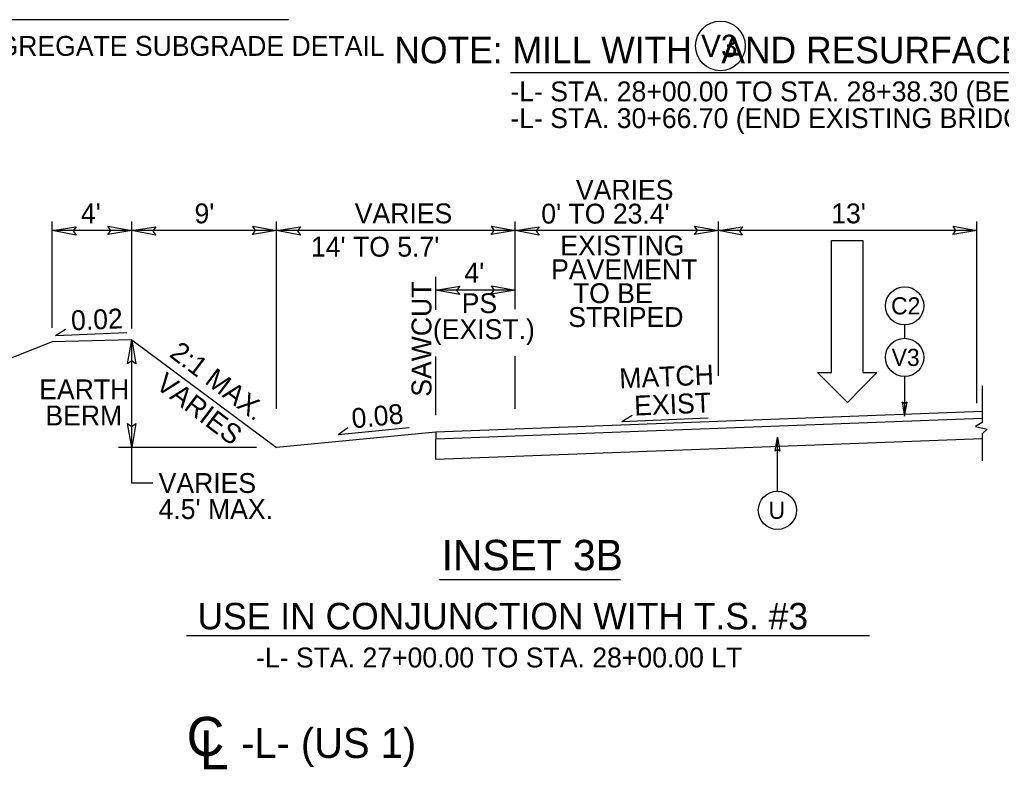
# Model space of a CAD drawing. Extents: x 573748 to 574632, y -54663 to -53209.
# Drawn here: x 574091.7 to 574165.8, y -53610.6 to -53554 of the extents above; entities that cross this region are included whole.
import ezdxf

# ---------------------------------------------------------------- set-up
doc = ezdxf.new("R2010")
doc.units = 0
for name, color, linetype in [('Prop Dimension', 7, 'Continuous'), ('Prop Dimension Text', 7, 'Continuous'), ('Prop Lane Arrow CELL', 7, 'Continuous'), ('Prop Terminator CELL', 7, 'Continuous'), ('Typical Arrow Superelevation CELL', 7, 'Continuous'), ('Typical Hinge Slope Arterial CELL', 7, 'Continuous'), ('Typical ID Circle CELL', 7, 'Continuous'), ('Typical Pavement Slope CELL', 7, 'Continuous'), ('Typical Terminator CELL', 7, 'Continuous'), ('Typical Text Centerline CELL', 7, 'Continuous'), ('Typical Text General CELL', 7, 'Continuous'), ('Typical Text ID Circle CELL', 7, 'Continuous'), ('Typical Text Label CELL', 7, 'Continuous')]:
    doc.layers.add(name, color=color, linetype=linetype)

# ---------------------------------------------------------------- blocks, each defined once
blk = doc.blocks.new('CENTERLINE TEXT CL')
at = {"layer": 'Typical Text Centerline CELL'}
blk.add_text('C', height=1.64, dxfattribs=at).set_placement((-0.546, -0.261))
blk.add_text('L', height=1.641, rotation=359.9469, dxfattribs=at).set_placement((-0.001, -0.821))

msp = doc.modelspace()

# ---------------------------------------------------------------- linework, layer by layer
at = {"layer": 'Prop Dimension'}
for p, q in [((574094.142, -53577.298), (574094.142, -53569.267)), ((574100.142, -53577.356), (574100.142, -53569.267)), ((574111.073, -53583.407), (574111.073, -53569.267)), ((574129.073, -53575.898), (574129.073, -53569.267)), ((574144.407, -53580.921), (574144.407, -53569.267)), ((574163.907, -53582.97), (574163.907, -53569.267)), ((574100.142, -53569.96), (574094.142, -53569.96)), ((574111.073, -53569.96), (574100.142, -53569.96)), ((574129.073, -53569.96), (574111.073, -53569.96)), ((574144.407, -53569.96), (574129.073, -53569.96)), ((574163.907, -53569.96), (574144.407, -53569.96)), ((574123.073, -53575.928), (574123.073, -53573.444)), ((574129.073, -53574.447), (574123.073, -53574.447)), ((574123.073, -53583.877), (574123.073, -53579.471)), ((574129.073, -53583.407), (574129.073, -53579.441)), ((574164.31, -53581.668), (574164.31, -53584.443)), ((574164.31, -53584.443), (574163.804, -53584.739)), ((574163.804, -53584.739), (574164.669, -53584.936)), ((574164.669, -53584.936), (574164.31, -53585.286)), ((574164.31, -53585.678), (574123.073, -53587.221)), ((574123.073, -53587.221), (574123.073, -53585.691)), ((574164.31, -53585.286), (574164.31, -53587.339)), ((574109.555, -53586.326), (574099.145, -53586.326))]:
    msp.add_line(p, q, dxfattribs=at)
msp.add_lwpolyline([(574101.742, -53589.024), (574100.142, -53589.024), (574100.142, -53578.213)], dxfattribs=at)
at = {"layer": 'Prop Lane Arrow CELL'}
for p, q in [((574152.941, -53580.677), (574152.941, -53570.702)), ((574152.941, -53570.702), (574155.292, -53570.702)), ((574155.292, -53570.702), (574155.292, -53580.677)), ((574154.152, -53582.922), (574151.872, -53580.677)), ((574151.872, -53580.677), (574152.941, -53580.677)), ((574156.361, -53580.677), (574154.152, -53582.922)), ((574155.292, -53580.677), (574156.361, -53580.677))]:
    msp.add_line(p, q, dxfattribs=at)
at = {"layer": 'Prop Terminator CELL'}
for points in [[(574095.939, -53570.293), (574094.142, -53569.96), (574095.957, -53569.663), (574095.723, -53569.98)], [(574098.346, -53569.627), (574100.142, -53569.96), (574098.328, -53570.257), (574098.562, -53569.939)], [(574101.939, -53570.293), (574100.142, -53569.96), (574101.957, -53569.663), (574101.723, -53569.98)], [(574109.277, -53569.627), (574111.073, -53569.96), (574109.258, -53570.257), (574109.493, -53569.939)], [(574112.869, -53570.293), (574111.073, -53569.96), (574112.888, -53569.663), (574112.653, -53569.98)], [(574127.277, -53569.627), (574129.073, -53569.96), (574127.258, -53570.257), (574127.493, -53569.939)], [(574130.869, -53570.293), (574129.073, -53569.96), (574130.888, -53569.663), (574130.653, -53569.98)], [(574142.611, -53569.627), (574144.407, -53569.96), (574142.592, -53570.257), (574142.827, -53569.939)], [(574146.203, -53570.293), (574144.407, -53569.96), (574146.222, -53569.663), (574145.987, -53569.98)], [(574162.111, -53569.627), (574163.907, -53569.96), (574162.092, -53570.257), (574162.327, -53569.939)], [(574124.869, -53574.781), (574123.073, -53574.447), (574124.888, -53574.151), (574124.653, -53574.468)], [(574127.277, -53574.114), (574129.073, -53574.447), (574127.258, -53574.744), (574127.493, -53574.427)], [(574099.832, -53580.014), (574100.142, -53578.213), (574100.462, -53580.024), (574100.142, -53579.794)], [(574100.452, -53584.526), (574100.142, -53586.326), (574099.822, -53584.516), (574100.142, -53584.746)]]:
    msp.add_lwpolyline(points, close=True, dxfattribs=at)
at = {"layer": 'Typical Arrow Superelevation CELL'}
for p, q in [((574094.384, -53577.88), (574095.156, -53577.39)), ((574094.384, -53577.88), (574099.773, -53577.657)), ((574137.12, -53584.368), (574137.892, -53583.877)), ((574137.12, -53584.368), (574143.638, -53584.088)), ((574115.705, -53585.347), (574121.072, -53584.805)), ((574115.705, -53585.347), (574116.447, -53584.812))]:
    msp.add_line(p, q, dxfattribs=at)
at = {"layer": 'Typical Hinge Slope Arterial CELL'}
for p, q in [((574094.142, -53578.346), (574071.464, -53587.365)), ((574100.142, -53578.213), (574094.142, -53578.346)), ((574100.142, -53578.213), (574111.073, -53586.326))]:
    msp.add_line(p, q, dxfattribs=at)
at = {"layer": 'Typical ID Circle CELL'}
for p, q in [((574158.452, -53577.08), (574158.452, -53578.085)), ((574158.452, -53580.971), (574158.452, -53583.957)), ((574148.857, -53589.623), (574148.857, -53585.539))]:
    msp.add_line(p, q, dxfattribs=at)
for centre, radius in [((574144.55, -53556.021), 1.875), ((574158.452, -53575.638), 1.443), ((574158.452, -53579.528), 1.443), ((574148.857, -53591.065), 1.443)]:
    msp.add_circle(centre, radius, dxfattribs=at)
at = {"layer": 'Typical Pavement Slope CELL'}
for p, q in [((574164.31, -53583.621), (574123.073, -53585.164)), ((574164.31, -53584.148), (574123.073, -53585.691)), ((574123.073, -53585.164), (574111.073, -53586.326)), ((574123.073, -53585.164), (574123.073, -53585.691))]:
    msp.add_line(p, q, dxfattribs=at)
at = {"layer": 'Typical Terminator CELL'}
for points in [[(574158.271, -53582.903), (574158.452, -53583.957), (574158.64, -53582.897), (574158.452, -53583.031)], [(574148.676, -53586.594), (574148.857, -53585.539), (574149.045, -53586.599), (574148.857, -53586.465)]]:
    msp.add_lwpolyline(points, close=True, dxfattribs=at)
at = {"layer": 'Typical Text General CELL'}
for p, q in [((574128.708, -53558.022), (574181.37, -53558.022)), ((574155.804, -53600.549), (574104.275, -53600.549))]:
    msp.add_line(p, q, dxfattribs=at)
at = {"layer": 'Typical Text Label CELL'}
for p, q in [((574071.117, -53554.037), (574111.959, -53554.037)), ((574137.016, -53596.317), (574123.356, -53596.317))]:
    msp.add_line(p, q, dxfattribs=at)

# ---------------------------------------------------------------- block references
at = {"layer": 'Prop Dimension', "xscale": 1.8000000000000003, "yscale": 1.8000000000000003}
msp.add_blockref('CENTERLINE TEXT CL', (574105.266, -53609.136), dxfattribs=at)

# ---------------------------------------------------------------- texts
at = {"layer": 'Prop Dimension Text'}
for s, height, p in [('VARIES', 1.5, (574133.654, -53567.629)), ("4'", 1.5, (574096.311, -53569.41)), ("9'", 1.5, (574104.879, -53569.41)), ('VARIES', 1.5, (574116.969, -53569.41)), ("0' TO 23.4'", 1.5, (574131.04, -53569.429)), ("13'", 1.5, (574152.912, -53569.41)), ('EXISTING', 1.5, (574132.477, -53571.831)), ("14' TO 5.7'", 1.5, (574113.663, -53571.922)), ("4'", 1.5, (574125.242, -53573.89)), ('PAVEMENT', 1.5, (574131.785, -53573.631)), ('TO BE', 1.5, (574133.427, -53575.431)), ('PS', 1.5, (574125.036, -53576.182)), ('STRIPED', 1.5, (574133.076, -53577.231)), ('(EXIST.)', 1.5, (574122.863, -53578.149)), ('EARTH', 1.5, (574093.164, -53582.691)), ('BERM', 1.5, (574093.632, -53584.657)), ('VARIES', 1.5, (574102.169, -53589.757)), ("4.5' MAX.", 1.5, (574102.169, -53591.723)), ('INSET 3B', 2.3, (574123.521, -53595.597)), ('-L- (US 1)', 2.25, (574108.393, -53609.754))]:
    msp.add_text(s, height=height, dxfattribs=at).set_placement(p)
for s, rotation, p in [('SAWCUT', 90, (574122.752, -53582.494)), ('0.02', 2.37567, (574095.594, -53577.488)), ('2:1 MAX.', 322.78983, (574102.907, -53579.411)), ('VARIES', 322.78983, (574101.86, -53581.778)), ('MATCH', 2.45213, (574136.958, -53581.867)), ('EXIST', 2.45213, (574138.081, -53583.921)), ('0.08', 5.76879, (574116.81, -53584.891))]:
    msp.add_text(s, height=1.5, rotation=rotation, dxfattribs=at).set_placement(p)
at = {"layer": 'Typical Text General CELL'}
for s, height, p in [('SEE SHEET 2A-6 FOR AGGREGATE SUBGRADE DETAIL', 1.5, (574065.719, -53556.772)), ('NOTE: MILL WITH   AND RESURFACE WITH ', 2, (574119.958, -53557.333)), ('-L- STA. 28+00.00 TO STA. 28+38.30 (BEGIN EXISTING BRIDGE)', 1.5, (574128.708, -53560.203)), ('-L- STA. 30+66.70 (END EXISTING BRIDGE) TO STA. 30+86.00', 1.5, (574128.708, -53562.219)), ('USE IN CONJUNCTION WITH T.S. #3', 2, (574105.106, -53600.052)), ('-L- STA. 27+00.00 TO STA. 28+00.00 LT', 1.5, (574109.526, -53602.922))]:
    msp.add_text(s, height=height, dxfattribs=at).set_placement(p)
at = {"layer": 'Typical Text ID Circle CELL'}
for s, height, p in [('V3', 1.6786, (574143.099, -53556.856)), ('C2', 1.2912, (574157.432, -53576.281)), ('V3', 1.2912, (574157.474, -53580.171)), ('U', 1.291, (574148.187, -53591.708))]:
    msp.add_text(s, height=height, dxfattribs=at).set_placement(p)

doc.saveas('drawing.dxf')
